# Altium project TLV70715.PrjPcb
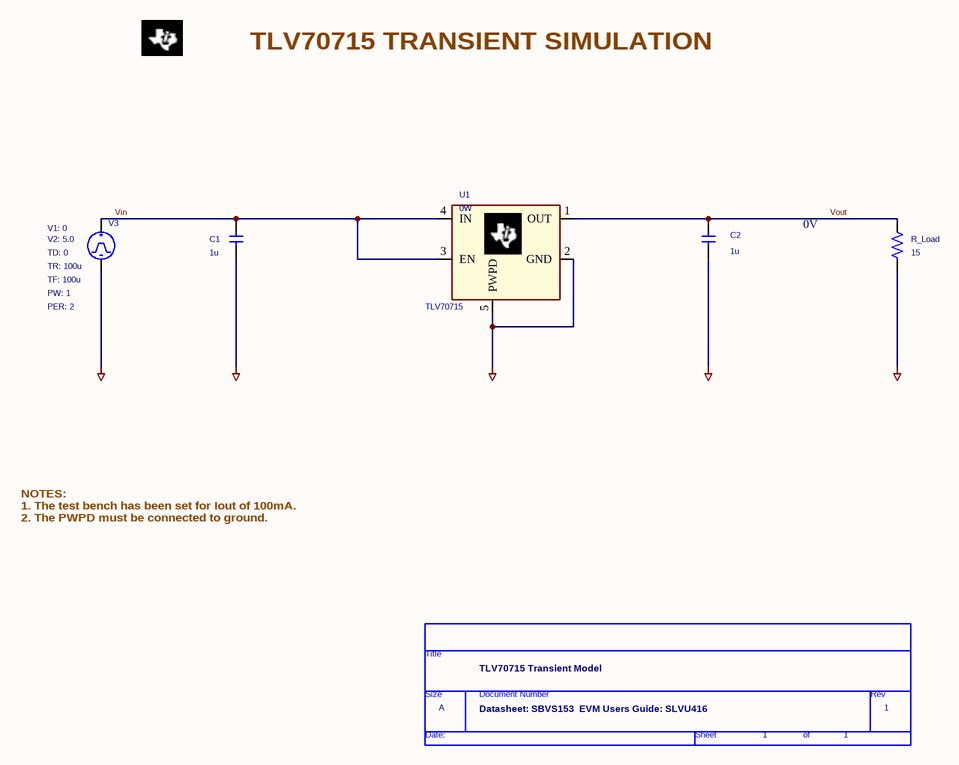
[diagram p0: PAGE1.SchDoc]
1 sheet, 6 parts. Net scope: global (net labels, ports and power ports of the same name join across sheets).

## Sheet PAGE1.SchDoc
size Letter

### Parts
*  Page Count: 1  Page Size: A  Title: TLV70715 Transient Model  Doc: Datasheet: SBVS153  EVM Users Guide: SLVU416  (hidden comment: TitleBlock0)  (graphical)
C1  1u  [RAD/CK05]
C2  1u  [RAD/CK05]
R_Load  15  [AX/RC05]
U1  TLV70715  BiasValue Power: 0W
V3  PER: 2  PW: 1  TF: 100u  TD: 0  V2: 5.0  (hidden comment: VPULSE)

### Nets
0: C1.1 C2.1 R_Load.1 U1.2(GND) U1.5(PWPD) V3.2(-)
Vin: C1.2 U1.3(EN) U1.4(IN) V3.1(+)
Vout: C2.2 R_Load.2 U1.1(OUT)

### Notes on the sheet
- TLV70715 TRANSIENT SIMULATION
- 0V
- NOTES:
  1. The test bench has been set for Iout of 100mA.
  2. The PWPD must be connected to ground.

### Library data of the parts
C1 C2 = C: TC2: 0; DIST: FLAT; PSpiceTemplate: C^@REFDES %1 %2 ?TOLERANCE¦C^@REFDES¦ @VALUE ?IC/IC=@IC/ TC=@TC1,@TC2 ?TOLERANCE¦\n.model C^@REFDES CAP C=1 DEV=@TOLERANCE%¦; VOLTAGE: CMAX; CURRENT: CIMAX; KNEE: CBMAX; SLOPE: CSMAX; MAX_TEMP: CTMAX
R_Load = R: TC2: 0; POWER: RMAX; MAX_TEMP: RTMAX; SLOPE: RSMAX; VOLTAGE: RVMAX; PSpiceTemplate: R^@REFDES %1 %2 ?TOLERANCE¦R^@REFDES¦ @VALUE TC=@TC1,@TC2 ?TOLERANCE¦\n.model R^@REFDES RES R=1 DEV=@TOLERANCE%¦; DIST: FLAT; BiasValue Power: 0W
U1 = TLV70715: PSpiceTemplate: X^@REFDES %OUT %GND %EN %IN %PWPD @MODEL
V3 = VPULSE: PSpiceTemplate: V^@REFDES %+ %- ?DC¦DC @DC¦ ?AC¦AC @AC¦\n+PULSE @V1 @V2 ?TD/@TD/~TD/0/ #TR/@TR/ #TF/@TF/ #PW/@PW/ #PER/@PER/; PSpiceOnly: TRUE; BiasValue Power: 0W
